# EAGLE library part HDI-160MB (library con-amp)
AMP connector
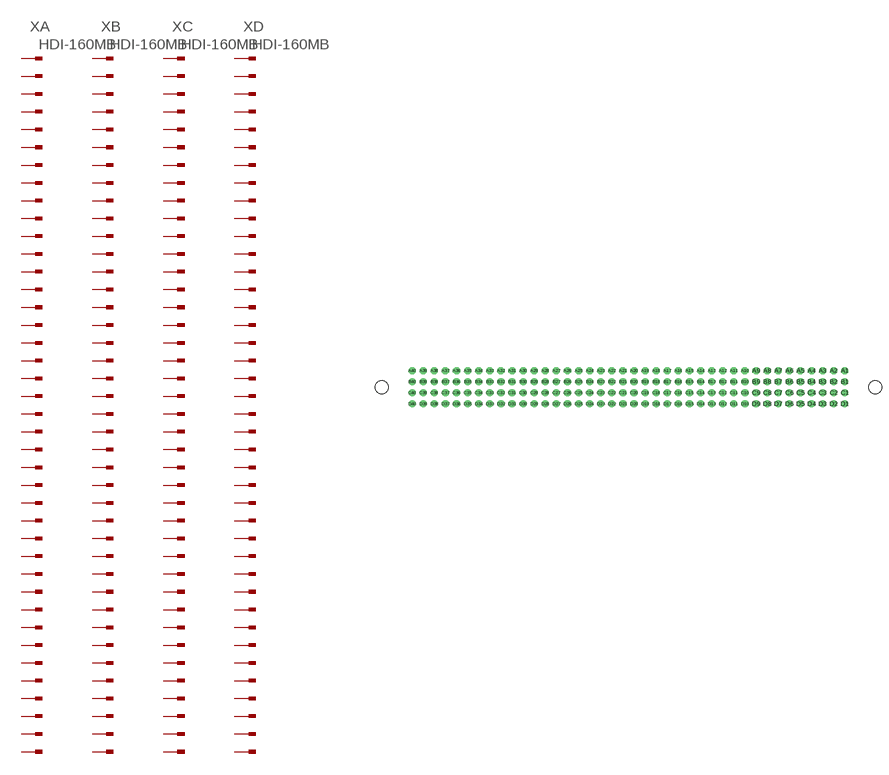
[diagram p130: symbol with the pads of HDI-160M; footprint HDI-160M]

Designator prefix X; gates A=PIN40M B=PIN40M C=PIN40M D=PIN40M

## HDI-160MB (OC_FARNELL: unknown; OC_NEWARK: unknown)  [HDI-160M]
A1  A:1  pas
A2  A:2  pas
A3  A:3  pas
A4  A:4  pas
A5  A:5  pas
A6  A:6  pas
A7  A:7  pas
A8  A:8  pas
A9  A:9  pas
A10  A:10  pas
A11  A:11  pas
A12  A:12  pas
A13  A:13  pas
A14  A:14  pas
A15  A:15  pas
A16  A:16  pas
A17  A:17  pas
A18  A:18  pas
A19  A:19  pas
A20  A:20  pas
A21  A:21  pas
A22  A:22  pas
A23  A:23  pas
A24  A:24  pas
A25  A:25  pas
A26  A:26  pas
A27  A:27  pas
A28  A:28  pas
A29  A:29  pas
A30  A:30  pas
A31  A:31  pas
A32  A:32  pas
A33  A:33  pas
A34  A:34  pas
A35  A:35  pas
A36  A:36  pas
A37  A:37  pas
A38  A:38  pas
A39  A:39  pas
A40  A:40  pas
B1  B:1  pas
B2  B:2  pas
B3  B:3  pas
B4  B:4  pas
B5  B:5  pas
B6  B:6  pas
B7  B:7  pas
B8  B:8  pas
B9  B:9  pas
B10  B:10  pas
B11  B:11  pas
B12  B:12  pas
B13  B:13  pas
B14  B:14  pas
B15  B:15  pas
B16  B:16  pas
B17  B:17  pas
B18  B:18  pas
B19  B:19  pas
B20  B:20  pas
B21  B:21  pas
B22  B:22  pas
B23  B:23  pas
B24  B:24  pas
B25  B:25  pas
B26  B:26  pas
B27  B:27  pas
B28  B:28  pas
B29  B:29  pas
B30  B:30  pas
B31  B:31  pas
B32  B:32  pas
B33  B:33  pas
B34  B:34  pas
B35  B:35  pas
B36  B:36  pas
B37  B:37  pas
B38  B:38  pas
B39  B:39  pas
B40  B:40  pas
C1  C:1  pas
C2  C:2  pas
C3  C:3  pas
C4  C:4  pas
C5  C:5  pas
C6  C:6  pas
C7  C:7  pas
C8  C:8  pas
C9  C:9  pas
C10  C:10  pas
C11  C:11  pas
C12  C:12  pas
C13  C:13  pas
C14  C:14  pas
C15  C:15  pas
C16  C:16  pas
C17  C:17  pas
C18  C:18  pas
C19  C:19  pas
C20  C:20  pas
C21  C:21  pas
C22  C:22  pas
C23  C:23  pas
C24  C:24  pas
C25  C:25  pas
C26  C:26  pas
C27  C:27  pas
C28  C:28  pas
C29  C:29  pas
C30  C:30  pas
C31  C:31  pas
C32  C:32  pas
C33  C:33  pas
C34  C:34  pas
C35  C:35  pas
C36  C:36  pas
C37  C:37  pas
C38  C:38  pas
C39  C:39  pas
C40  C:40  pas
D1  D:1  pas
D2  D:2  pas
D3  D:3  pas
D4  D:4  pas
D5  D:5  pas
D6  D:6  pas
D7  D:7  pas
D8  D:8  pas
D9  D:9  pas
D10  D:10  pas
D11  D:11  pas
D12  D:12  pas
D13  D:13  pas
D14  D:14  pas
D15  D:15  pas
D16  D:16  pas
D17  D:17  pas
D18  D:18  pas
D19  D:19  pas
D20  D:20  pas
D21  D:21  pas
D22  D:22  pas
D23  D:23  pas
D24  D:24  pas
D25  D:25  pas
D26  D:26  pas
D27  D:27  pas
D28  D:28  pas
D29  D:29  pas
D30  D:30  pas
D31  D:31  pas
D32  D:32  pas
D33  D:33  pas
D34  D:34  pas
D35  D:35  pas
D36  D:36  pas
D37  D:37  pas
D38  D:38  pas
D39  D:39  pas
D40  D:40  pas

## Footprint HDI-160M (pad centres in mm)
AMP connector
drill 1.09 octagon: A1 49.53,3.81; A2 46.99,3.81; A3 44.45,3.81; A4 41.91,3.81; A5 39.37,3.81; A6 36.83,3.81; A7 34.29,3.81; A8 31.75,3.81; A9 29.21,3.81; A10 26.67,3.81; A11 24.13,3.81; A12 21.59,3.81; A13 19.05,3.81; A14 16.51,3.81; A15 13.97,3.81; A16 11.43,3.81; A17 8.89,3.81; A18 6.35,3.81; A19 3.81,3.81; A20 1.27,3.81; A21 -1.27,3.81; A22 -3.81,3.81; A23 -6.35,3.81; A24 -8.89,3.81; A25 -11.43,3.81; A26 -13.97,3.81; A27 -16.51,3.81; A28 -19.05,3.81; A29 -21.59,3.81; A30 -24.13,3.81; A31 -26.67,3.81; A32 -29.21,3.81; A33 -31.75,3.81; A34 -34.29,3.81; A35 -36.83,3.81; A36 -39.37,3.81; A37 -41.91,3.81; A38 -44.45,3.81; A39 -46.99,3.81; A40 -49.53,3.81
drill 1.09 round: B1 49.53,1.27; B2 46.99,1.27; B3 44.45,1.27; B4 41.91,1.27; B5 39.37,1.27; B6 36.83,1.27; B7 34.29,1.27; B8 31.75,1.27; B9 29.21,1.27; B10 26.67,1.27; B11 24.13,1.27; B12 21.59,1.27; B13 19.05,1.27; B14 16.51,1.27; B15 13.97,1.27; B16 11.43,1.27; B17 8.89,1.27; B18 6.35,1.27; B19 3.81,1.27; B20 1.27,1.27; B21 -1.27,1.27; B22 -3.81,1.27; B23 -6.35,1.27; B24 -8.89,1.27; B25 -11.43,1.27; B26 -13.97,1.27; B27 -16.51,1.27; B28 -19.05,1.27; B29 -21.59,1.27; B30 -24.13,1.27; B31 -26.67,1.27; B32 -29.21,1.27; B33 -31.75,1.27; B34 -34.29,1.27; B35 -36.83,1.27; B36 -39.37,1.27; B37 -41.91,1.27; B38 -44.45,1.27; B39 -46.99,1.27; B40 -49.53,1.27; C1 49.53,-1.27; C2 46.99,-1.27; C3 44.45,-1.27; C4 41.91,-1.27; C5 39.37,-1.27; C6 36.83,-1.27; C7 34.29,-1.27; C8 31.75,-1.27; C9 29.21,-1.27; C10 26.67,-1.27; C11 24.13,-1.27; C12 21.59,-1.27; C13 19.05,-1.27; C14 16.51,-1.27; C15 13.97,-1.27; C16 11.43,-1.27; C17 8.89,-1.27; C18 6.35,-1.27; C19 3.81,-1.27; C20 1.27,-1.27; C21 -1.27,-1.27; C22 -3.81,-1.27; C23 -6.35,-1.27; C24 -8.89,-1.27; C25 -11.43,-1.27; C26 -13.97,-1.27; C27 -16.51,-1.27; C28 -19.05,-1.27; C29 -21.59,-1.27; C30 -24.13,-1.27; C31 -26.67,-1.27; C32 -29.21,-1.27; C33 -31.75,-1.27; C34 -34.29,-1.27; C35 -36.83,-1.27; C36 -39.37,-1.27; C37 -41.91,-1.27; C38 -44.45,-1.27; C39 -46.99,-1.27; C40 -49.53,-1.27; D1 49.53,-3.81; D2 46.99,-3.81; D3 44.45,-3.81; D4 41.91,-3.81; D5 39.37,-3.81; D6 36.83,-3.81; D7 34.29,-3.81; D8 31.75,-3.81; D9 29.21,-3.81; D10 26.67,-3.81; D11 24.13,-3.81; D12 21.59,-3.81; D13 19.05,-3.81; D14 16.51,-3.81; D15 13.97,-3.81; D16 11.43,-3.81; D17 8.89,-3.81; D18 6.35,-3.81; D19 3.81,-3.81; D20 1.27,-3.81; D21 -1.27,-3.81; D22 -3.81,-3.81; D23 -6.35,-3.81; D24 -8.89,-3.81; D25 -11.43,-3.81; D26 -13.97,-3.81; D27 -16.51,-3.81; D28 -19.05,-3.81; D29 -21.59,-3.81; D30 -24.13,-3.81; D31 -26.67,-3.81; D32 -29.21,-3.81; D33 -31.75,-3.81; D34 -34.29,-3.81; D35 -36.83,-3.81; D36 -39.37,-3.81; D37 -41.91,-3.81; D38 -44.45,-3.81; D39 -46.99,-3.81; D40 -49.53,-3.81
hole 3.05 at -56.51,0
hole 3.05 at 56.51,0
